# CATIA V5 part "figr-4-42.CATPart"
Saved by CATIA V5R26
Part number: Part1
Bounding box of the stored display mesh (mm): x -59.931 to 60.019, y -73.049 to 76.86, z -59.931 to 60.019
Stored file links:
  D:\_Deepak\CATIA\CATIA V5-6R2016_Deepak\Resources\Part files\Partfiles\c04_catia_v5_6r2016_prt\figr-4-42.CATPart
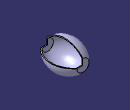
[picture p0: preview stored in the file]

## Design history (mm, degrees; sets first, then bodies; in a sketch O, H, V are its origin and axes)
Body1 (main body)
  Sketch1 on yz-plane, origin (0, 0, 0), H (0, 1, 0), V (0, 0, 1)
    point P1 (76.8601, 0)
    line L1 (76.8601, 0) -> (76.8601, 25)
    construction line L2 through (0, 0) direction (-1, 0)
    point P5 (-73.049, 0)
    line L3 (-73.049, 0) -> (-73.049, 25)
    axis line L4 (-100, 0) -> (100, 0)
    arc A1 centre (1.9056, -37.7079) radius 97.7265 from (76.8601, 25) to (-73.049, 25) ccw
    point P10 (0, 60)
    length L1 = 25
    length L3 = 25
    horizontal: L4 H
    vertical: L3 V, L1 V
    coincidence: P1 L4, L4 L2, P5 L4, L4 H, A1 P10, P10 V
  Shaft1: profile Sketch1, axis Sketch1.L4, angle 270, thin wall 4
